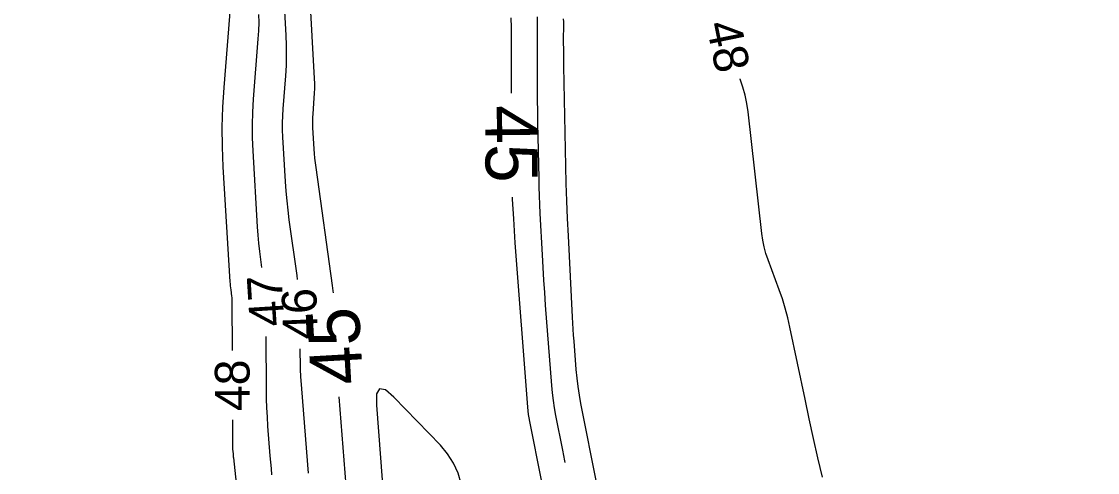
# Model space of a CAD drawing. Extents: x 2384780 to 2405861, y 547869 to 573706.
# Drawn here: x 2393472.2 to 2393534.2, y 552405.2 to 552431.2 of the extents above; entities that cross this region are included whole.
import ezdxf

# ---------------------------------------------------------------- set-up
doc = ezdxf.new("R2010")
doc.units = 0
for name, color, linetype in [('Old_Level_60', 7, 'Continuous'), ('Old_Level_61', 7, 'Continuous'), ('Old_Level_63', 7, 'Continuous')]:
    doc.layers.add(name, color=color, linetype=linetype)

msp = doc.modelspace()

# ---------------------------------------------------------------- linework, layer by layer
at = {"layer": 'Old_Level_60'}
for points in [[(2393487.1585, 552435.8845), (2393487.46575, 552430.40275), (2393487.48875, 552429.8195), (2393487.49175, 552429.23675), (2393487.47525, 552428.65425), (2393487.439, 552428.07175)], [(2393484.30975, 552432.73675), (2393483.8875, 552427.401), (2393483.817, 552426.25725), (2393483.78625, 552425.1135), (2393483.79525, 552423.969), (2393483.84425, 552422.82425), (2393484.24325, 552416.19475), (2393484.251, 552416.08125), (2393484.26125, 552415.968), (2393484.27375, 552415.855), (2393484.28825, 552415.74225), (2393484.33975, 552415.374), (2393484.3495, 552415.295), (2393484.35625, 552415.21575), (2393484.36075, 552415.1365), (2393484.36225, 552415.057), (2393484.371, 552412.24775)], [(2393485.898, 552431.59675), (2393485.9005, 552431.1315), (2393485.88725, 552430.66625), (2393485.85825, 552430.2015)], [(2393503.568, 552405.782), (2393503.5485, 552405.8795), (2393503.42675, 552406.49275), (2393503.02825, 552408.4965), (2393502.94925, 552408.9265), (2393502.8835, 552409.35875), (2393502.8305, 552409.7925), (2393502.7905, 552410.228), (2393502.43575, 552414.8465), (2393502.38225, 552415.57325), (2393502.33325, 552416.3005), (2393502.289, 552417.02825), (2393502.24925, 552417.756), (2393502.1265, 552420.134), (2393502.10225, 552420.64375), (2393502.082, 552421.1535), (2393502.066, 552421.6635), (2393502.054, 552422.1735), (2393501.9915, 552425.33525), (2393501.97975, 552426.01275), (2393501.97175, 552426.69025), (2393501.967, 552427.36775), (2393501.96575, 552428.04525), (2393501.9675, 552430.73775), (2393501.96575, 552431.09925), (2393501.96, 552431.4605)], [(2393505.407, 552404.45875), (2393504.46825, 552409.1785), (2393504.3785, 552409.668), (2393504.3035, 552410.1595), (2393504.24325, 552410.65325), (2393504.19775, 552411.14875), (2393504.07325, 552412.771), (2393504.0475, 552413.11875), (2393504.02425, 552413.4665), (2393504.003, 552413.8145), (2393503.984, 552414.16275), (2393503.74225, 552418.8485), (2393503.6945, 552419.85275), (2393503.65475, 552420.85725), (2393503.623, 552421.86225), (2393503.599, 552422.86725), (2393503.4855, 552428.6205), (2393503.47975, 552428.9545), (2393503.47575, 552429.2885), (2393503.4735, 552429.62225), (2393503.473, 552429.95625), (2393503.47375, 552431.1775), (2393503.473, 552431.34625)], [(2393485.85825, 552430.2015), (2393485.58325, 552426.7245), (2393485.53725, 552425.97925), (2393485.51725, 552425.23375), (2393485.52325, 552424.48825), (2393485.555, 552423.74225), (2393485.81825, 552419.3685), (2393485.8515, 552418.89325), (2393485.894, 552418.419), (2393485.946, 552417.94575), (2393486.00725, 552417.47325), (2393486.0695, 552417.027)], [(2393487.439, 552428.07175), (2393487.2885, 552426.16975), (2393487.26325, 552425.762), (2393487.2525, 552425.35425), (2393487.25575, 552424.94625), (2393487.27325, 552424.53825), (2393487.42775, 552421.96825), (2393487.46625, 552421.418), (2393487.5155, 552420.869), (2393487.57575, 552420.321), (2393487.6465, 552419.774), (2393488.0945, 552416.56525), (2393488.12375, 552416.328)], [(2393518.3805, 552404.93175), (2393518.12375, 552406.0535), (2393517.8725, 552407.17675), (2393517.62725, 552408.301), (2393517.3875, 552409.42675), (2393516.514, 552413.5815), (2393516.38825, 552414.12925), (2393516.2425, 552414.67125), (2393516.07675, 552415.20725), (2393515.89075, 552415.73775), (2393515.251, 552417.46075), (2393515.1255, 552417.83275), (2393515.02325, 552418.2105), (2393514.94425, 552418.5935), (2393514.8885, 552418.982), (2393514.0985, 552425.994), (2393514.02925, 552426.475), (2393513.93075, 552426.949), (2393513.80275, 552427.416), (2393513.6455, 552427.87575), (2393513.64075, 552427.888)], [(2393486.32175, 552413.042), (2393486.33125, 552409.98825), (2393486.33775, 552409.462), (2393486.35425, 552408.93625), (2393486.38025, 552408.41075), (2393486.41625, 552407.88575), (2393486.54975, 552406.1715), (2393486.57975, 552405.80425), (2393486.6125, 552405.43725), (2393486.64775, 552405.0705)], [(2393488.277, 552412.33425), (2393488.278, 552412.031), (2393488.2835, 552411.59325), (2393488.297, 552411.156), (2393488.31875, 552410.71875), (2393488.34875, 552410.282), (2393488.71025, 552405.6415), (2393488.7485, 552405.171)], [(2393498.206, 552401.70875), (2393497.5745, 552404.55025), (2393497.3915, 552405.174), (2393497.1295, 552405.755), (2393496.78875, 552406.2935), (2393496.36875, 552406.7895), (2393493.69675, 552409.5495), (2393493.20375, 552409.9645), (2393492.87, 552410.0265), (2393492.69525, 552409.73525), (2393492.6795, 552409.091), (2393493.1335, 552403.2645), (2393493.135, 552403.246), (2393493.1365, 552403.2275), (2393493.13825, 552403.209), (2393493.14025, 552403.1905)], [(2393484.3835, 552408.24775), (2393484.38775, 552406.87875), (2393484.389, 552406.79725), (2393484.3915, 552406.71575), (2393484.3955, 552406.63425), (2393484.401, 552406.55275), (2393484.42175, 552406.287), (2393484.4265, 552406.23), (2393484.4315, 552406.17325), (2393484.437, 552406.11625), (2393484.44275, 552406.0595), (2393485.07225, 552400.1975)]]:
    msp.add_lwpolyline(points, dxfattribs=at)
at = {"layer": 'Old_Level_61'}
for points in [[(2393488.57, 552437.33575), (2393489.099, 552427.9025), (2393489.11, 552427.622), (2393489.1115, 552427.34175), (2393489.1035, 552427.0615), (2393489.08625, 552426.7815)], [(2393500.45925, 552427.07625), (2393500.46125, 552430.298), (2393500.45875, 552430.85225), (2393500.44975, 552431.40625)], [(2393489.08625, 552426.7815), (2393489.01375, 552425.86675), (2393489.00175, 552425.67075), (2393488.9965, 552425.4745), (2393488.998, 552425.27825), (2393489.0065, 552425.082), (2393489.08075, 552423.84625), (2393489.09925, 552423.5815), (2393489.123, 552423.3175), (2393489.152, 552423.054), (2393489.186, 552422.79075), (2393490.1375, 552415.97675), (2393490.174, 552415.6785), (2393490.18475, 552415.5545)], [(2393501.7125, 552407.18875), (2393501.5225, 552408.14475), (2393501.48475, 552408.35025), (2393501.45325, 552408.55625), (2393501.428, 552408.76325), (2393501.409, 552408.97125), (2393500.682, 552418.44), (2393500.65625, 552418.787), (2393500.633, 552419.134), (2393500.61175, 552419.48125), (2393500.59275, 552419.8285), (2393500.53425, 552420.96325), (2393500.529, 552421.077)], [(2393490.5235, 552409.56675), (2393490.92125, 552404.461)], [(2393503.302, 552399.16325), (2393501.945, 552406.018), (2393501.887, 552406.31075), (2393501.82875, 552406.60325), (2393501.77075, 552406.896), (2393501.7125, 552407.18875)]]:
    msp.add_lwpolyline(points, dxfattribs=at)
at = {"layer": 'Old_Level_63'}
msp.add_circle((2393492.91434, 552580.66252), 187.93516, dxfattribs=at)

# ---------------------------------------------------------------- texts
at = {"layer": 'Old_Level_60'}
for s, rotation, p in [('48', 281.5420361, (2393511.67975, 552431.041)), ('47', 93.6203333, (2393487.393, 552413.67475)), ('46', 92.1990611, (2393489.3225, 552412.8935)), ('48', 90.1795139, (2393485.382, 552408.747))]:
    msp.add_text(s, height=2, rotation=rotation, dxfattribs=at).set_placement(p)
at = {"layer": 'Old_Level_61'}
for rotation, p in [(270.666275, (2393498.934, 552426.3615)), (93.2371194, (2393491.91825, 552410.34325))]:
    msp.add_text('45', height=3, rotation=rotation, dxfattribs=at).set_placement(p)

doc.saveas('drawing.dxf')
